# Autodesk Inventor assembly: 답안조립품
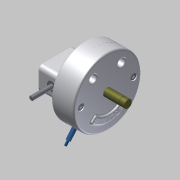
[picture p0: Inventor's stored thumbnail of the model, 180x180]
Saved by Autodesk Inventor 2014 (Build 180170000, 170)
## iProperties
Created: 2015-04
Part Number: 답안조립품
Document SubType Name: Assembly
Designer: Administrator
Mass: 3435.4 g
Surface Area: 3333.71 cm^2
Volume: 1140.85 cm^3
Density: 3.01126 g/cm^3
Author: Administrator
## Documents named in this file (15)
- C:\Documents and Settings\Administrator\바탕 화면\350406V1015\답안조립품.iam
- C:\Documents and Settings\Administrator\바탕 화면\350406V1015\본체.ipt
- C:\Documents and Settings\Administrator\바탕 화면\350406V1015\커버.ipt
- C:\Documents and Settings\Administrator\바탕 화면\350406V1015\가변스프링.ipt
- C:\Documents and Settings\Administrator\바탕 화면\350406V1015\축.ipt
- C:\Documents and Settings\Administrator\바탕 화면\350406V1015\멈춤링.ipt
- C:\Documents and Settings\Administrator\바탕 화면\350406V1015\베어링62_22.ipt
- C:\Documents and Settings\Administrator\바탕 화면\350406V1015\M 10 x 35.ipt
- C:\Documents and Settings\Administrator\바탕 화면\350406V1015\커버2.ipt
- C:\Documents and Settings\Administrator\바탕 화면\350406V1015\M 5 x 12.ipt
- C:\Documents and Settings\Administrator\바탕 화면\350406V1015\슬라이더2.ipt
- C:\Documents and Settings\Administrator\바탕 화면\350406V1015\슬라이더.ipt
- C:\Documents and Settings\Administrator\바탕 화면\350406V1015\평행핀.ipt
- C:\Documents and Settings\Administrator\바탕 화면\350406V1015\슬라이더3.ipt
- C:\Documents and Settings\Administrator\바탕 화면\350406V1015\부시.ipt
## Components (6 placed, 4 different names)
1. M 10 x 35:1
2. M 10 x 35:2
3. M 5 x 12:1
4. M 5 x 12:2
5. KS B 1320 B B 5 x  20:1 — 플러쉬:1
6. 가변스프링:1
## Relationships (1: Flush 1)
- 플러쉬:1 [Flush]: KS B 1320 B B 5 x  20:1
